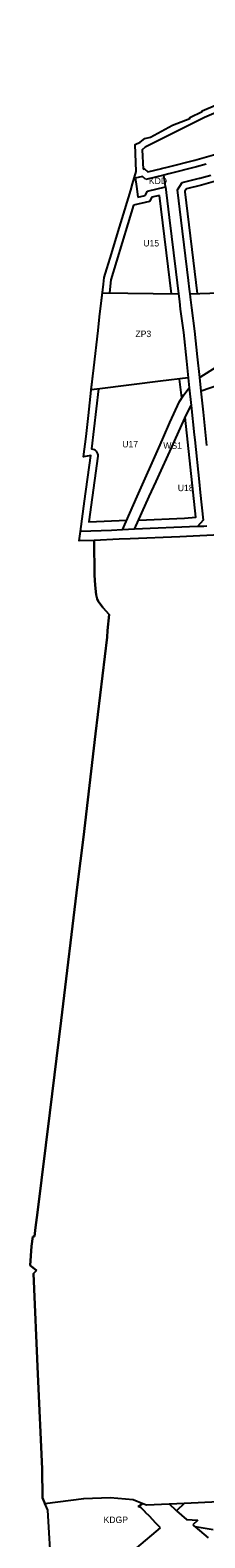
# Model space of a CAD drawing. Extents: x 7428080 to 7432143, y 5545880 to 5549217.
# Drawn here: x 7428670 to 7428821, y 5547123 to 5548419 of the extents above; entities that cross this region are included whole.
import ezdxf

# ---------------------------------------------------------------- set-up
doc = ezdxf.new("R2010")
doc.units = 0
for name, color, linetype in [('CZ_L_granica obszaru objętego planem', 7, 'Continuous'), ('CZ_L_linie rozgraniczające tereny o różnym przeznaczeniu oraz różnych warunkach ich zabudowy i zagospodarowania', 7, 'Continuous'), ('CZ_L_maksymalne nieprzekraczalne linie zabudowy', 7, 'Continuous'), ('CZ_L_opisy_linie rozgraniczające tereny o różnym przeznaczeniu oraz różnych warunkach ich zabudowy i zagospodarowania', 7, 'Continuous'), ('info', 7, 'Continuous')]:
    doc.layers.add(name, color=color, linetype=linetype)

msp = doc.modelspace()

# ---------------------------------------------------------------- linework, layer by layer
at = {"layer": 'CZ_L_granica obszaru objętego planem'}
for p, q in [((7428818.5, 5548349.5), (7428849.1, 5548362.4)), ((7428808, 5548343.8), (7428818.5, 5548349)), ((7428818.5, 5548349), (7428818.5, 5548349.5)), ((7428774.1, 5548327), (7428793.1, 5548337.1)), ((7428793.1, 5548337.1), (7428808, 5548342.9)), ((7428808, 5548342.9), (7428808, 5548343.8)), ((7428760.8, 5548320.6), (7428765.2, 5548322.7)), ((7428761.9, 5548297.5), (7428760.8, 5548320.6)), ((7428765.2, 5548322.7), (7428769.3, 5548325.7)), ((7428769.3, 5548325.7), (7428774.1, 5548327)), ((7428758.6, 5548286.7), (7428761.9, 5548297.5)), ((7428752, 5548264.4), (7428757.1, 5548281.5)), ((7428757.1, 5548281.5), (7428758.6, 5548286.7)), ((7428747.5, 5548249.7), (7428752, 5548264.4)), ((7428739.4, 5548222.9), (7428747.5, 5548249.7)), ((7428736.6, 5548213.8), (7428739.4, 5548222.9)), ((7428733.6, 5548200.7), (7428734.2, 5548206.2)), ((7428734.2, 5548206.2), (7428736.6, 5548213.8)), ((7428730.3, 5548172.6), (7428733.6, 5548200.7)), ((7428728.9, 5548160.9), (7428730.3, 5548172.6)), ((7428725.2, 5548128.7), (7428728.9, 5548160.9)), ((7428723.1, 5548109.6), (7428725.2, 5548128.7)), ((7428720.7, 5548087.8), (7428723.1, 5548109.6)), ((7428718.6, 5548069.8), (7428720.7, 5548087.8)), ((7428716.5, 5548052.2), (7428718.6, 5548069.8)), ((7428722.7, 5548053.2), (7428716.5, 5548052.2)), ((7428717.3, 5548014), (7428722.7, 5548053.2)), ((7428713.7, 5547987.9), (7428717.3, 5548014)), ((7428712.6, 5547979.9), (7428713.7, 5547987.9)), ((7428725.5, 5547980.4), (7428712.6, 5547979.9)), ((7428725.9, 5547950.5), (7428725.5, 5547980.4)), ((7428726.3, 5547942), (7428725.9, 5547950.5)), ((7428727.3, 5547933.5), (7428726.3, 5547942)), ((7428728.3, 5547930.1), (7428727.3, 5547933.5)), ((7428729, 5547928.1), (7428728.3, 5547930.1)), ((7428733.1, 5547922.8), (7428729, 5547928.1)), ((7428738.5, 5547916.7), (7428733.1, 5547922.8)), ((7428737.2, 5547903), (7428738.5, 5547916.7)), ((7428726.8, 5547814.2), (7428736.7, 5547897.2)), ((7428736.7, 5547897.2), (7428737.2, 5547903)), ((7428716.3, 5547725.4), (7428726.8, 5547814.2)), ((7428711.2, 5547684.5), (7428716.3, 5547725.4)), ((7428697.2, 5547567.8), (7428711.2, 5547684.5)), ((7428687.4, 5547488.5), (7428697.2, 5547567.8)), ((7428676.7, 5547402.7), (7428687.4, 5547488.5)), ((7428675.1, 5547390), (7428676.7, 5547402.7)), ((7428674.2, 5547382), (7428675.1, 5547390)), ((7428670.4, 5547357.1), (7428671.5, 5547373.8)), ((7428671.5, 5547373.8), (7428672.7, 5547382.1)), ((7428672.7, 5547382.1), (7428674.2, 5547382)), ((7428671.3, 5547356.7), (7428670.4, 5547357.1)), ((7428675.9, 5547353), (7428671.3, 5547356.7)), ((7428673.2, 5547350.3), (7428675.9, 5547353)), ((7428677.1, 5547263.9), (7428673.2, 5547350.3)), ((7428680.8, 5547182.4), (7428677.1, 5547263.9)), ((7428681.2, 5547157.5), (7428680.8, 5547182.4)), ((7428685.6, 5547147), (7428681.2, 5547157.5)), ((7428689.1, 5547088.6), (7428685.6, 5547147))]:
    msp.add_line(p, q, dxfattribs=at)
at = {"layer": 'CZ_L_linie rozgraniczające tereny o różnym przeznaczeniu oraz różnych warunkach ich zabudowy i zagospodarowania'}
for p, q in [((7428785.5, 5548294.4), (7428770.1, 5548290.6)), ((7428789.9, 5548295.3), (7428785.5, 5548294.4)), ((7428785.5, 5548294.3), (7428785.5, 5548294.4)), ((7428786.9, 5548284.4), (7428785.5, 5548294.3)), ((7428813.8, 5548301.3), (7428789.9, 5548295.3)), ((7428822, 5548303.6), (7428813.8, 5548301.3)), ((7428816.5, 5548291.6), (7428826, 5548294.3)), ((7428767.3, 5548293.2), (7428760.9, 5548291.6)), ((7428760.9, 5548291.6), (7428761.4, 5548288.5)), ((7428761.4, 5548288.5), (7428762.2, 5548282.5)), ((7428762.2, 5548282.5), (7428763.3, 5548275.4)), ((7428770.1, 5548290.6), (7428767.3, 5548293.2)), ((7428769.4, 5548276.9), (7428771.4, 5548280.6)), ((7428771.4, 5548280.6), (7428786.9, 5548284.3)), ((7428786.9, 5548284.3), (7428786.9, 5548284.4)), ((7428786.9, 5548284.3), (7428787.6, 5548279.3)), ((7428800.6, 5548255.6), (7428797.4, 5548281.6)), ((7428797.4, 5548281.6), (7428797.5, 5548281.6)), ((7428797.5, 5548281.6), (7428801.5, 5548287.9)), ((7428801.5, 5548287.9), (7428816.3, 5548291.6)), ((7428816.3, 5548291.6), (7428816.4, 5548291.6)), ((7428816.4, 5548291.6), (7428816.5, 5548291.6)), ((7428763.3, 5548275.4), (7428769.4, 5548276.9)), ((7428787.6, 5548279.3), (7428790.2, 5548258)), ((7428790.2, 5548258), (7428795.9, 5548211.3)), ((7428806.9, 5548203.8), (7428800.6, 5548255.6)), ((7428795.9, 5548211.3), (7428798.2, 5548192.4)), ((7428807.8, 5548196.4), (7428806.9, 5548203.8)), ((7428732.7, 5548193.2), (7428798.2, 5548192.4)), ((7428798.2, 5548192.4), (7428799, 5548185.7)), ((7428808.3, 5548192.3), (7428807.8, 5548196.4)), ((7428808.3, 5548192.3), (7428937.3, 5548196.4)), ((7428808.6, 5548189.5), (7428808.3, 5548192.3)), ((7428799, 5548185.7), (7428799.8, 5548179)), ((7428799.8, 5548179), (7428802.5, 5548159.1)), ((7428809.7, 5548180.1), (7428808.6, 5548189.5)), ((7428812.4, 5548160.2), (7428809.7, 5548180.1)), ((7428802.5, 5548159.1), (7428805.1, 5548134.3)), ((7428814.7, 5548138.2), (7428812.4, 5548160.2)), ((7428816.6, 5548120.3), (7428814.7, 5548138.2)), ((7428805.1, 5548134.3), (7428806.6, 5548120)), ((7428836.2, 5548132.8), (7428816.6, 5548120.3)), ((7428782.7, 5548117.2), (7428730.4, 5548110.5)), ((7428806.6, 5548120), (7428782.7, 5548117.2)), ((7428806.6, 5548120), (7428807.5, 5548111.4)), ((7428817.8, 5548108.6), (7428816.6, 5548120.3)), ((7428832.8, 5548113.7), (7428817.8, 5548108.6)), ((7428730.4, 5548110.5), (7428723.1, 5548109.8)), ((7428790.9, 5548081.6), (7428799, 5548099.6)), ((7428799, 5548099.6), (7428802.7, 5548105.5)), ((7428802.7, 5548105.5), (7428807.5, 5548111.4)), ((7428807.5, 5548111.4), (7428809.1, 5548096.2)), ((7428819.7, 5548090.7), (7428817.8, 5548108.6)), ((7428795.8, 5548068.1), (7428805.2, 5548088.7)), ((7428805.2, 5548088.7), (7428809.1, 5548096.2)), ((7428809.1, 5548096.2), (7428811.7, 5548071)), ((7428822.7, 5548062), (7428819.7, 5548090.7)), ((7428785.2, 5548069), (7428790.9, 5548081.6)), ((7428762.7, 5548018), (7428782.3, 5548062.5)), ((7428778.9, 5548031), (7428793.6, 5548063.1)), ((7428782.3, 5548062.5), (7428782.4, 5548062.6)), ((7428782.4, 5548062.6), (7428785.2, 5548069)), ((7428793.6, 5548063.1), (7428795.8, 5548068.1)), ((7428811.7, 5548071), (7428812.2, 5548066.7)), ((7428812.2, 5548066.7), (7428816, 5548030.7)), ((7428773.1, 5548018.1), (7428778.9, 5548031)), ((7428816, 5548030.7), (7428817, 5548021.5)), ((7428817, 5548021.5), (7428819.5, 5547997.7)), ((7428750.1, 5547989.4), (7428762.7, 5548018)), ((7428760.3, 5547989.9), (7428773.1, 5548018.1)), ((7428819.5, 5547997.7), (7428814.5, 5547992.2)), ((7428740.6, 5547989), (7428713.7, 5547988)), ((7428750.1, 5547989.4), (7428740.6, 5547989)), ((7428760.3, 5547989.9), (7428750.1, 5547989.4)), ((7428814.5, 5547992.2), (7428760.3, 5547989.9)), ((7428820, 5547992.4), (7428814.5, 5547992.2)), ((7428822.7, 5547992.6), (7428820, 5547992.4)), ((7428685.6, 5547147), (7428683.2, 5547152.7)), ((7428689.1, 5547088.6), (7428685.6, 5547147)), ((7428763.4, 5547150), (7428767.4, 5547152.8)), ((7428766.1, 5547148.9), (7428763.4, 5547150)), ((7428769.9, 5547145.1), (7428766.1, 5547148.9)), ((7428769.9, 5547145), (7428769.9, 5547145.1)), ((7428773.2, 5547141.7), (7428769.9, 5547145)), ((7428776.1, 5547138.6), (7428773.2, 5547141.7)), ((7428796.5, 5547146.5), (7428790.3, 5547152.4)), ((7428803.4, 5547153), (7428796.5, 5547146.5)), ((7428796.5, 5547146.5), (7428796.6, 5547146.4)), ((7428796.6, 5547146.4), (7428805.2, 5547139)), ((7428762.2, 5547114.7), (7428782.7, 5547131.7)), ((7428778.4, 5547136.1), (7428776.1, 5547138.6)), ((7428781.9, 5547132.5), (7428778.4, 5547136.1)), ((7428782.7, 5547131.7), (7428781.9, 5547132.5)), ((7428805.2, 5547139), (7428814.9, 5547138.4)), ((7428814.9, 5547138.4), (7428810.6, 5547134.3)), ((7428810.6, 5547134.3), (7428810.7, 5547134.3)), ((7428810.7, 5547134.3), (7428811.5, 5547133.6)), ((7428811.5, 5547133.6), (7428812.7, 5547132.5)), ((7428812.7, 5547132.5), (7428823.9, 5547123.1)), ((7428814.3, 5547132.2), (7428812.7, 5547132.5)), ((7428828, 5547129.9), (7428814.3, 5547132.2))]:
    msp.add_line(p, q, dxfattribs=at)
for points in [[(7428732.7, 5548193.2), (7428733.6, 5548200.7), (7428734.2, 5548206.2), (7428736.6, 5548213.8), (7428739.4, 5548222.9), (7428747.5, 5548249.7), (7428752, 5548264.4), (7428757.1, 5548281.5), (7428758.6, 5548286.7), (7428761.9, 5548297.5), (7428760.8, 5548320.6), (7428765.2, 5548322.7), (7428769.3, 5548325.7), (7428774.1, 5548327), (7428793.1, 5548337.1), (7428808, 5548342.9), (7428808, 5548343.8), (7428818.5, 5548349), (7428818.5, 5548349.5), (7428849.1, 5548362.4)], [(7428723.1, 5548109.8), (7428725.2, 5548128.7), (7428728.9, 5548160.9), (7428730.3, 5548172.6), (7428732.7, 5548193.2)], [(7428713.7, 5547988), (7428717.3, 5548014), (7428722.7, 5548053.2), (7428716.5, 5548052.2), (7428718.6, 5548069.8), (7428720.7, 5548087.8), (7428723.1, 5548109.6), (7428723.1, 5548109.8)], [(7428725.5, 5547980.3), (7428725.5, 5547980.4), (7428712.6, 5547979.9), (7428713.7, 5547987.9), (7428713.7, 5547988)]]:
    msp.add_lwpolyline(points, dxfattribs=at)
at = {"layer": 'CZ_L_maksymalne nieprzekraczalne linie zabudowy'}
for points in [[(7429005.8, 5548386.7), (7428991.3, 5548418.9), (7428917.1, 5548385.7), (7428873.2, 5548366.3), (7428820.7, 5548343.9), (7428769.6, 5548318.3), (7428767, 5548316.1), (7428767.8, 5548299.5)], [(7428783.7, 5548300.1), (7428789.6, 5548301.4), (7428812.4, 5548307.1), (7428846.5, 5548316.8), (7428875.6, 5548326.7), (7428898.6, 5548335.5), (7428915, 5548342.9), (7429005.1, 5548384.9), (7429005.8, 5548386.7)], [(7428898.7, 5548311.9), (7428882.6, 5548305.8), (7428867, 5548300.5), (7428848.1, 5548294.4), (7428818.1, 5548285.8), (7428805.2, 5548282.5), (7428803.8, 5548280.4), (7428803.7, 5548279.9), (7428814.3, 5548192.5)], [(7428767.8, 5548299.5), (7428768.9, 5548299.8), (7428771.8, 5548297.2), (7428783.8, 5548300.1)], [(7428759.4, 5548268.5), (7428740, 5548204.2), (7428738.8, 5548193.2)], [(7428781.9, 5548276.9), (7428775.4, 5548275.4), (7428773.2, 5548271.6), (7428759.5, 5548268.6)], [(7428792.1, 5548192.4), (7428781.9, 5548276.9)], [(7428801, 5548103), (7428799.2, 5548118.8)], [(7428729.2, 5548110.7), (7428723.3, 5548059.1), (7428724.4, 5548058.9), (7428725.5, 5548058.5), (7428726.5, 5548057.9), (7428727.4, 5548057), (7428728, 5548056), (7428728.5, 5548054.9), (7428728.7, 5548053.8), (7428728.7, 5548052.7), (7428720.9, 5547996.4), (7428753.7, 5547997.8)], [(7428764, 5547997.9), (7428803.4, 5547999.4), (7428813.2, 5548000.2), (7428804.1, 5548086.4)]]:
    msp.add_lwpolyline(points, dxfattribs=at)
at = {"layer": 'info'}
for p, q in [((7428725.5, 5547980.3), (7428725.9, 5547950.5)), ((7428725.9, 5547950.5), (7428726.3, 5547942)), ((7428726.3, 5547942), (7428727.3, 5547933.5)), ((7428727.3, 5547933.5), (7428728.3, 5547930.1)), ((7428728.3, 5547930.1), (7428729, 5547928.1)), ((7428729, 5547928.1), (7428733.1, 5547922.8)), ((7428733.1, 5547922.8), (7428738.5, 5547916.7)), ((7428738.5, 5547916.7), (7428737.2, 5547903)), ((7428736.7, 5547897.2), (7428726.8, 5547814.2)), ((7428737.2, 5547903), (7428736.7, 5547897.2)), ((7428726.8, 5547814.2), (7428716.3, 5547725.4)), ((7428716.3, 5547725.4), (7428711.2, 5547684.5)), ((7428711.2, 5547684.5), (7428697.2, 5547567.8)), ((7428697.2, 5547567.8), (7428687.4, 5547488.5)), ((7428687.4, 5547488.5), (7428676.7, 5547402.7)), ((7428676.7, 5547402.7), (7428675.1, 5547390)), ((7428675.1, 5547390), (7428674.2, 5547382)), ((7428671.5, 5547373.8), (7428670.4, 5547357.1)), ((7428672.7, 5547382.1), (7428671.5, 5547373.8)), ((7428674.2, 5547382), (7428672.7, 5547382.1)), ((7428670.4, 5547357.1), (7428671.3, 5547356.7)), ((7428671.3, 5547356.7), (7428675.9, 5547353)), ((7428675.9, 5547353), (7428673.2, 5547350.3)), ((7428673.2, 5547350.3), (7428677.1, 5547263.9)), ((7428677.1, 5547263.9), (7428680.8, 5547182.4)), ((7428680.8, 5547182.4), (7428681.2, 5547157.5)), ((7428681.2, 5547157.5), (7428683.2, 5547152.7))]:
    msp.add_line(p, q, dxfattribs=at)
for points in [[(7428839.9, 5547985.4), (7428799.3, 5547983.4), (7428756.6, 5547981.6), (7428747.1, 5547981.3), (7428725.5, 5547980.3)], [(7428683.2, 5547152.7), (7428716.7, 5547157), (7428739.5, 5547157.9), (7428759.3, 5547156.2), (7428767.4, 5547152.8), (7428770.6, 5547151.4), (7428790.3, 5547152.4), (7428803.4, 5547153), (7428891.3, 5547157.3)]]:
    msp.add_lwpolyline(points, dxfattribs=at)

# ---------------------------------------------------------------- texts
at = {"layer": 'CZ_L_opisy_linie rozgraniczające tereny o różnym przeznaczeniu oraz różnych warunkach ich zabudowy i zagospodarowania'}
for s, p in [('KDD', (7428772.7, 5548286.6)), ('U15', (7428767.9, 5548233)), ('ZP3', (7428761.1, 5548155.1)), ('U17', (7428749.8, 5548060.3)), ('WS1', (7428785.1, 5548059.1)), ('U18', (7428797.6, 5548022.7)), ('KDGP', (7428733.7, 5547135.9))]:
    msp.add_text(s, height=5.55, dxfattribs=at).set_placement(p)

doc.saveas('drawing.dxf')
